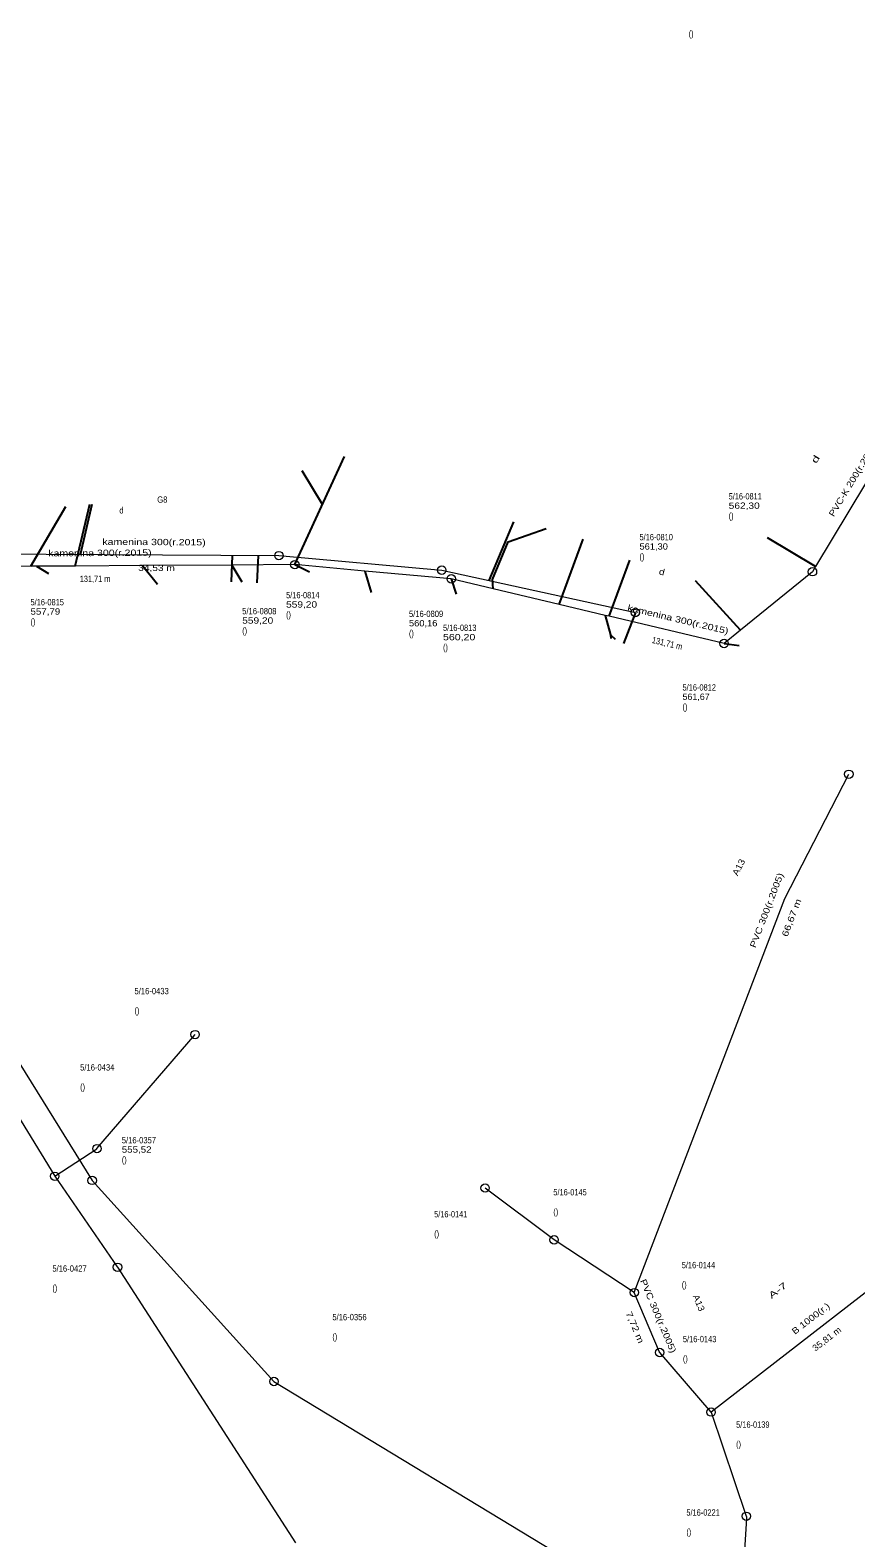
# Model space of a CAD drawing. Extents: x -710854 to -709799, y -1117012 to -1115891.
# Drawn here: x -710481.9 to -710384, y -1116503.5 to -1116324.5 of the extents above; entities that cross this region are included whole.
import ezdxf
from ezdxf.enums import TextEntityAlignment as Align

# ---------------------------------------------------------------- set-up
doc = ezdxf.new("R2010")
doc.units = 0
doc.header["$LTSCALE"] = 0.3
for name, color, linetype, lineweight in [('35', 7, 'Continuous', 25), ('36', 7, 'Continuous', 13), ('37', 7, 'Continuous', 13), ('38', 7, 'Continuous', 13), ('44', 7, 'Continuous', 13)]:
    doc.layers.add(name, color=color, linetype=linetype, lineweight=lineweight)
doc.layers.add('48', color=7, linetype='Continuous')

msp = doc.modelspace()

# ---------------------------------------------------------------- linework, layer by layer
at = {"layer": '35'}
for p, q in [((-710450.53, -1116387.94), (-710444.63, -1116375.11)), ((-710447.24, -1116380.78), (-710449.66, -1116376.82)), ((-710481.86, -1116388.13), (-710477.69, -1116381.03)), ((-710476.59, -1116388.1), (-710474.86, -1116380.74)), ((-710475.95, -1116386.73), (-710474.58, -1116380.74)), ((-710427.49, -1116389.82), (-710424.55, -1116382.86)), ((-710388.76, -1116388.16), (-710394.45, -1116384.75)), ((-710419.17, -1116392.66), (-710416.34, -1116384.93)), ((-710481.19, -1116388.13), (-710479.735, -1116388.99)), ((-710468.59, -1116388.05), (-710466.82, -1116390.25)), ((-710457.95, -1116386.84), (-710458.09, -1116389.96)), ((-710458.002, -1116387.99), (-710456.82, -1116389.99)), ((-710454.9, -1116386.86), (-710455.04, -1116390.1)), ((-710450.53, -1116387.94), (-710448.795, -1116388.81)), ((-710413.25, -1116394.07), (-710410.79, -1116387.41)), ((-710442.21, -1116388.7), (-710441.47, -1116391.25)), ((-710431.97, -1116389.62), (-710431.396, -1116391.45)), ((-710397.67, -1116395.72), (-710403.02, -1116389.86)), ((-710410.14, -1116393.63), (-710411.557, -1116397.314)), ((-710413.08, -1116396.27), (-710412.52, -1116396.78)), ((-710399.62, -1116397.3), (-710397.81, -1116397.52))]:
    msp.add_line(p, q, dxfattribs=at)
for points in [[(-710427, -1116390.8), (-710427.08, -1116389.7), (-710425.24, -1116385.25), (-710420.73, -1116383.65)], [(-710413.7, -1116393.96), (-710413.08, -1116396.27), (-710413.03, -1116396.71)]]:
    msp.add_lwpolyline(points, dxfattribs=at)
at = {"layer": '36'}
msp.add_line((-710453.004, -1116484.913), (-710396.742, -1116519.013), dxfattribs=at)
for points in [[(-710378.88, -1116371.72), (-710388.76, -1116388.16), (-710389.13, -1116388.78)], [(-710450.53, -1116387.94), (-710457.99, -1116387.99), (-710468.56, -1116388.05), (-710476.59, -1116388.1), (-710481.19, -1116388.13), (-710481.86, -1116388.13), (-710486.59, -1116388.16)], [(-710431.97, -1116389.62), (-710442.21, -1116388.7), (-710450.53, -1116387.94)], [(-710399.62, -1116397.3), (-710413.25, -1116394.07), (-710413.7, -1116393.96), (-710419.17, -1116392.66), (-710427, -1116390.8), (-710431.97, -1116389.62)], [(-710389.13, -1116388.78), (-710397.67, -1116395.72), (-710399.62, -1116397.3)], [(-710506.893, -1116396.918), (-710492.96, -1116431.46), (-710474.57, -1116461.041)], [(-710474.57, -1116461.041), (-710453.021, -1116484.902), (-710453.004, -1116484.913)]]:
    msp.add_lwpolyline(points, dxfattribs=at)
at = {"layer": '37'}
msp.add_lwpolyline([(-710486.95, -1116386.67), (-710452.42, -1116386.87), (-710433.11, -1116388.59), (-710410.14, -1116393.63)], dxfattribs=at)
at = {"layer": '38'}
msp.add_line((-710401.16, -1116488.54), (-710396.975, -1116500.905), dxfattribs=at)
for points in [[(-710410.26, -1116474.36), (-710392.39, -1116427.57), (-710384.81, -1116412.82)], [(-710490.428, -1116441.873), (-710490.41, -1116441.91), (-710490.378, -1116441.962), (-710479.01, -1116460.54)], [(-710479.01, -1116460.54), (-710474.03, -1116457.3), (-710474.028, -1116457.297), (-710474.001, -1116457.266), (-710462.37, -1116443.73)], [(-710479.01, -1116460.54), (-710471.6, -1116471.29), (-710471.59, -1116471.305), (-710471.566, -1116471.343), (-710450.451, -1116504.072)], [(-710410.26, -1116474.36), (-710419.76, -1116468.11), (-710419.766, -1116468.106), (-710419.782, -1116468.093), (-710427.97, -1116461.94)], [(-710372.847, -1116466.61), (-710372.86, -1116466.62), (-710401.16, -1116488.54)], [(-710407.254, -1116481.471), (-710407.278, -1116481.414), (-710410.26, -1116474.36)], [(-710401.16, -1116488.54), (-710407.25, -1116481.48), (-710407.254, -1116481.471)], [(-710396.975, -1116500.905), (-710396.96, -1116500.95), (-710396.972, -1116501.151), (-710398.3, -1116522.9)]]:
    msp.add_lwpolyline(points, dxfattribs=at)
at = {"layer": '44'}
for centre in [(-710452.42, -1116386.87), (-710450.53, -1116387.94), (-710433.11, -1116388.59), (-710389.13, -1116388.78), (-710431.97, -1116389.62), (-710410.14, -1116393.63), (-710399.62, -1116397.3), (-710384.81, -1116412.82), (-710462.37, -1116443.73), (-710474.001, -1116457.266), (-710479.01, -1116460.54), (-710474.57, -1116461.041), (-710427.97, -1116461.94), (-710419.782, -1116468.093), (-710471.566, -1116471.343), (-710410.26, -1116474.36), (-710407.254, -1116481.471), (-710453.004, -1116484.913), (-710401.16, -1116488.54), (-710396.975, -1116500.905)]:
    msp.add_circle(centre, 0.5, dxfattribs=at)

# ---------------------------------------------------------------- texts
at = {"layer": '48'}
for s, width, p in [('()', 0.7, (-710403.812, -1116325.278)), ('5/16-0811', 0.8, (-710399.067, -1116380.202)), ('562,30 ', 1.2, (-710399.067, -1116381.312)), ('()', 0.7, (-710399.067, -1116382.512)), ('5/16-0810', 0.85, (-710409.65, -1116385.042)), ('()', 0.7, (-710409.65, -1116387.352)), ('561,30 ', 1.1, (-710409.65, -1116386.152)), ('5/16-0815', 0.85, (-710481.889, -1116392.767)), ('5/16-0814', 0.85, (-710451.571, -1116391.927)), ('557,79 ', 1.15, (-710481.889, -1116393.877)), ('5/16-0808', 0.9, (-710456.775, -1116393.834)), ('()', 0.7, (-710451.571, -1116394.237)), ('559,20 ', 1.2, (-710451.571, -1116393.037)), ('5/16-0809', 0.9, (-710436.994, -1116394.157)), ('()', 0.7, (-710481.889, -1116395.077)), ('()', 0.7, (-710456.775, -1116396.144)), ('559,20 ', 1.2, (-710456.775, -1116394.944)), ('560,16 ', 1.1, (-710436.994, -1116395.267)), ('5/16-0813', 0.85, (-710432.954, -1116395.805)), ('()', 0.7, (-710436.994, -1116396.467)), ('()', 0.7, (-710432.954, -1116398.115)), ('560,20 ', 1.25, (-710432.954, -1116396.915)), ('5/16-0812', 0.85, (-710404.543, -1116402.884)), ('561,67 ', 1.05, (-710404.543, -1116403.994)), ('()', 0.7, (-710404.543, -1116405.194)), ('5/16-0433', 0.9, (-710469.549, -1116438.935)), ('()', 0.7, (-710469.549, -1116441.245)), ('5/16-0434', 0.9, (-710476, -1116447.993)), ('()', 0.7, (-710476, -1116450.303)), ('5/16-0357', 0.9, (-710471.059, -1116456.639)), ('()', 0.7, (-710471.059, -1116458.949)), ('555,52 ', 1.15, (-710471.059, -1116457.749)), ('5/16-0145', 0.85, (-710419.869, -1116462.815)), ('5/16-0141', 0.8, (-710434.004, -1116465.423)), ('()', 0.7, (-710419.869, -1116465.125)), ('()', 0.7, (-710434.004, -1116467.733)), ('5/16-0144', 0.85, (-710404.635, -1116471.461)), ('5/16-0427', 0.9, (-710479.293, -1116471.873)), ('()', 0.7, (-710479.293, -1116474.183)), ('()', 0.7, (-710404.635, -1116473.771)), ('5/16-0356', 0.9, (-710446.081, -1116477.637)), ('()', 0.7, (-710446.081, -1116479.947)), ('5/16-0143', 0.85, (-710404.498, -1116480.245)), ('()', 0.7, (-710404.498, -1116482.555)), ('5/16-0139', 0.85, (-710398.185, -1116490.4)), ('()', 0.7, (-710398.185, -1116492.71)), ('5/16-0221', 0.85, (-710404.086, -1116500.831)), ('()', 0.7, (-710404.086, -1116503.141))]:
    msp.add_text(s, height=0.75, dxfattribs=dict(at, width=width)).set_placement(p)
for s, rotation, width, p in [('PVC-K 200(r.2015)', 59, 1.2, (-710383.9691, -1116377.9366)), ('d', 59, 1.65, (-710388.4506, -1116375.6096)), ('d', 0.36, 0.9, (-710471.0874, -1116381.8654)), ('G8', 359.67, 0.9, (-710466.2517, -1116380.5905)), ('kamenina 300(r.2015)', 359.67, 1.25, (-710467.2377, -1116385.6241)), ('kamenina 300(r.2015)', 0.36, 1.25, (-710473.6494, -1116386.9206)), ('34,53 m', 359.67, 1.2, (-710466.9407, -1116388.6955)), ('d', 346.67, 1.2, (-710407.0735, -1116389.1629)), ('131,71 m', 0.36, 0.8, (-710474.2239, -1116389.9946)), ('kamenina 300(r.2015)', 346.67, 1.25, (-710405.1565, -1116394.7949)), ('131,71 m', 346.67, 0.85, (-710406.4415, -1116397.6459)), ('A13', 62.8, 1.15, (-710397.5447, -1116424.0344)), ('PVC 300(r.2005)', 69.1, 1.25, (-710394.2169, -1116429.1023)), ('PVC 300(r.2005)', 69.1, 1.25, (-710394.2169, -1116429.1023)), ('66,67 m', 69.1, 1.3, (-710391.2668, -1116429.9848)), ('66,67 m', 69.1, 1.3, (-710391.2668, -1116429.9848)), ('PVC 300(r.2005)', 292.92, 1.25, (-710407.7678, -1116477.278)), ('A-7', 37.76, 1.55, (-710393.0211, -1116474.3931)), ('A13', 292.92, 1.15, (-710402.9509, -1116475.7265)), ('B 1000(r.)', 37.76, 1.2, (-710389.1011, -1116477.7333)), ('7,72 m', 292.92, 1.3, (-710410.5311, -1116478.6225)), ('35,81 m', 37.76, 1.1, (-710387.2041, -1116480.1463))]:
    msp.add_text(s, height=0.75, rotation=rotation, dxfattribs=dict(at, width=width)).set_placement(p, align=Align.CENTER)

doc.saveas('drawing.dxf')
